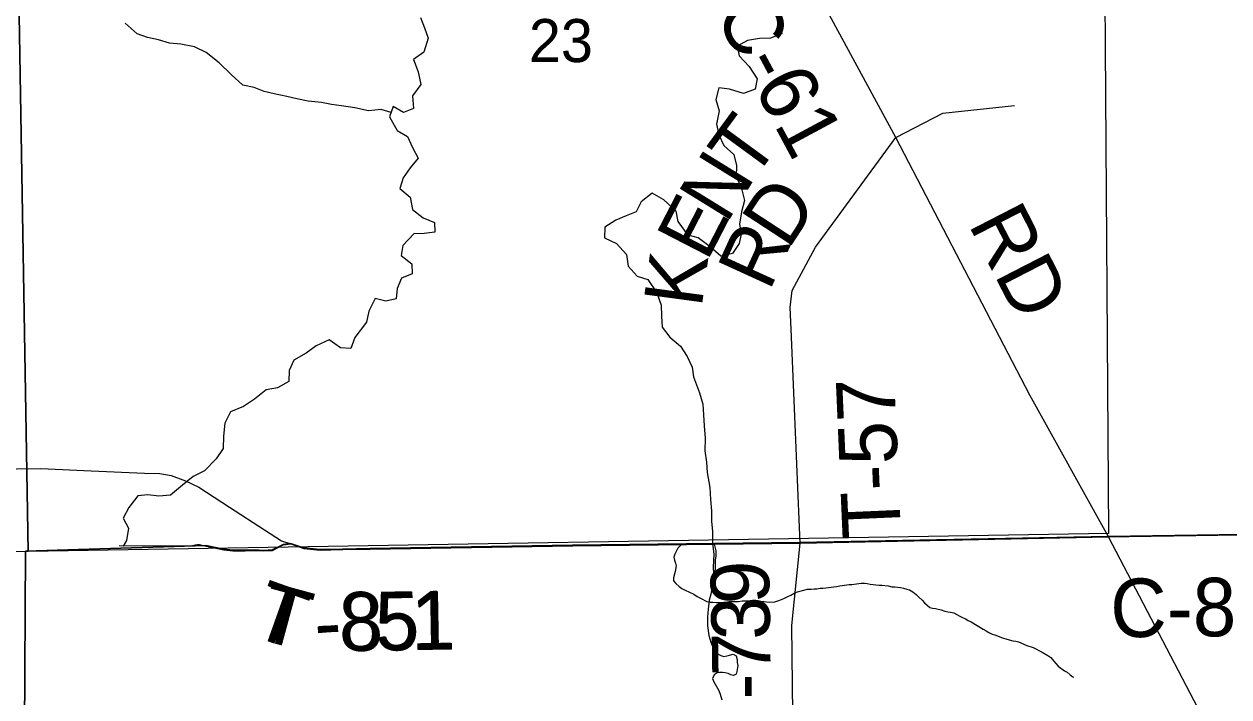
# Model space of a CAD drawing. Extents: x 0 to 34, y 0 to 22.
# Drawn here: x 3.443 to 4.614, y 19.097 to 19.751 of the extents above; entities that cross this region are included whole.
import ezdxf

# ---------------------------------------------------------------- set-up
doc = ezdxf.new("R2010")
doc.units = 0
for name, color, linetype in [('GM_X_County_Road', 7, 'Continuous'), ('GM_X_County_Road_Text', 7, 'Continuous'), ('GM_X_Minor_River', 7, 'Continuous'), ('GM_X_Rail_Line', 7, 'Continuous'), ('GM_X_Section', 7, 'Continuous'), ('GM_X_Section_Text', 7, 'Continuous'), ('GM_X_Township', 7, 'Continuous'), ('GM_X_Township_Road', 7, 'Continuous'), ('GM_X_Township_Road_Text', 7, 'Continuous'), ('SH_Cut_Line', 7, 'Continuous')]:
    doc.layers.add(name, color=color, linetype=linetype)

msp = doc.modelspace()

# ---------------------------------------------------------------- linework, layer by layer
at = {"layer": 'GM_X_County_Road'}
msp.add_line((4.497, 19.2526), (4.5168, 19.2529), dxfattribs=at)
for points in [[(4.497, 19.2526), (4.4208, 19.3901), (4.2904, 19.6406), (4.1777, 19.8488), (4.1636, 19.8791), (4.1541, 19.9074), (4.1442, 19.9366), (4.1303, 19.9782), (4.1198, 20.013), (4.1112, 20.041), (4.093, 20.0955), (4.0874, 20.1167), (4.0803, 20.1337), (4.0339, 20.1931), (4.0167, 20.23), (4.0013, 20.2492)], [(4.5168, 19.2529), (4.9933, 19.26), (5.2151, 19.2619), (5.5233, 19.2646)], [(4.634, 18.9904), (4.6257, 19.0064), (4.497, 19.2526)]]:
    msp.add_lwpolyline(points, dxfattribs=at)
at = {"layer": 'GM_X_Minor_River'}
for points in [[(3.8287, 19.757), (3.8326, 19.7472), (3.8361, 19.737), (3.832, 19.7236), (3.8219, 19.7163), (3.8265, 19.7042), (3.8289, 19.6921), (3.8207, 19.681), (3.8219, 19.6688), (3.8121, 19.665), (3.8022, 19.6706), (3.7985, 19.6607), (3.8058, 19.6474), (3.8161, 19.6414), (3.8208, 19.6309), (3.8262, 19.6206), (3.8187, 19.6111), (3.8119, 19.6015), (3.8086, 19.5909), (3.8186, 19.5826), (3.8209, 19.5705), (3.8312, 19.5626), (3.8423, 19.5581), (3.8424, 19.5486), (3.8321, 19.5474), (3.8223, 19.5469), (3.8114, 19.5358), (3.81, 19.5259), (3.8203, 19.5177), (3.8204, 19.5082), (3.8102, 19.5039), (3.8058, 19.494), (3.8051, 19.4837), (3.7949, 19.4817), (3.7846, 19.4843), (3.7783, 19.4717), (3.7762, 19.4611), (3.7649, 19.4462), (3.7609, 19.4355), (3.751, 19.4362), (3.74, 19.4441), (3.7272, 19.4383), (3.7174, 19.4309), (3.7057, 19.4244), (3.7009, 19.4141), (3.7006, 19.4035), (3.6897, 19.3973), (3.6787, 19.3953), (3.6674, 19.3865), (3.6565, 19.3792), (3.6441, 19.3741), (3.6385, 19.3631), (3.6371, 19.3505), (3.6368, 19.3384), (3.6301, 19.3284), (3.6189, 19.3166), (3.6079, 19.3111), (3.5974, 19.3027), (3.5858, 19.2931), (3.5744, 19.2922), (3.5638, 19.2933), (3.554, 19.2924), (3.5454, 19.281), (3.5398, 19.2707), (3.5448, 19.2609), (3.543, 19.2491), (3.5397, 19.2437)], [(3.8, 19.6647), (3.7905, 19.6678), (3.778, 19.6666), (3.7647, 19.6695), (3.7519, 19.6713), (3.742, 19.6727), (3.7325, 19.6745), (3.7196, 19.6759), (3.7086, 19.6781), (3.6988, 19.6803), (3.6866, 19.6829), (3.6768, 19.6851), (3.6669, 19.6892), (3.6559, 19.6914), (3.6448, 19.7019), (3.633, 19.7132), (3.6204, 19.723), (3.609, 19.7286), (3.5957, 19.7311), (3.5847, 19.7321), (3.5741, 19.7355), (3.5635, 19.7377), (3.5532, 19.7414), (3.5418, 19.7515)], [(4.1759, 19.7516), (4.1798, 19.7414), (4.1688, 19.7371), (4.1579, 19.7367), (4.1465, 19.7347), (4.1363, 19.7293), (4.1383, 19.7198), (4.1479, 19.7096), (4.1556, 19.6975), (4.1538, 19.6876), (4.1424, 19.6834), (4.1288, 19.6874), (4.1185, 19.6889), (4.1156, 19.6774), (4.1188, 19.6664), (4.1162, 19.6535), (4.1186, 19.6433), (4.1232, 19.6327), (4.1332, 19.624), (4.1355, 19.6134), (4.1353, 19.6024), (4.1403, 19.5922), (4.1434, 19.5793), (4.1405, 19.5683), (4.1387, 19.5565), (4.1403, 19.547), (4.1381, 19.5375), (4.1318, 19.5279), (4.1204, 19.5252), (4.1101, 19.5342), (4.0983, 19.5432), (4.0888, 19.5458), (4.0789, 19.559), (4.0769, 19.5689), (4.065, 19.5801), (4.0536, 19.5865), (4.0431, 19.5781), (4.0383, 19.5685), (4.0285, 19.5646), (4.0183, 19.5604), (4.0077, 19.5535), (4.0075, 19.5432), (4.0189, 19.5376), (4.0288, 19.527), (4.0304, 19.5157), (4.0392, 19.5059), (4.0495, 19.5025), (4.0583, 19.4897), (4.0626, 19.4776), (4.0627, 19.4669), (4.0635, 19.4563), (4.0708, 19.4465), (4.0811, 19.4379), (4.0877, 19.4277), (4.0927, 19.4174), (4.0939, 19.408), (4.0997, 19.3924), (4.1029, 19.3815)], [(4.1029, 19.3815), (4.1037, 19.3712), (4.1042, 19.3606), (4.1051, 19.3484), (4.1048, 19.3363), (4.1064, 19.3253), (4.1073, 19.315), (4.1097, 19.3006), (4.1105, 19.2888), (4.1114, 19.2778), (4.1115, 19.2676), (4.1123, 19.2581), (4.1124, 19.2467), (4.1137, 19.2353), (4.113, 19.2232), (4.1135, 19.2106), (4.1139, 19.2072)], [(4.082, 19.2447), (4.0786, 19.2416), (4.0757, 19.2359), (4.0749, 19.2328), (4.0754, 19.2298), (4.0765, 19.2272), (4.0769, 19.2245), (4.0762, 19.2188), (4.0744, 19.2127), (4.0744, 19.21), (4.0768, 19.2074), (4.0798, 19.2044), (4.0825, 19.2025), (4.0859, 19.2007), (4.0943, 19.197), (4.0974, 19.1947), (4.1008, 19.1929), (4.1069, 19.1899), (4.11, 19.1892), (4.1126, 19.1892), (4.116, 19.1889), (4.1225, 19.1889), (4.1255, 19.1893), (4.1282, 19.1898), (4.1376, 19.1899), (4.141, 19.1903), (4.1475, 19.1904), (4.1532, 19.1912), (4.1562, 19.1909), (4.1593, 19.1901), (4.1676, 19.1891), (4.1729, 19.1895), (4.1759, 19.1903), (4.1793, 19.1919), (4.1824, 19.1931), (4.1854, 19.1946), (4.1884, 19.1958), (4.1922, 19.1981), (4.1948, 19.1993), (4.2046, 19.2017), (4.2081, 19.2017), (4.2111, 19.2022), (4.2137, 19.2022), (4.2168, 19.2026), (4.2194, 19.2026), (4.2224, 19.203), (4.2327, 19.2043), (4.2361, 19.2051), (4.2452, 19.2064), (4.2478, 19.2064), (4.2569, 19.2076), (4.2599, 19.2077), (4.2626, 19.2073), (4.2656, 19.2066), (4.274, 19.2056), (4.277, 19.2056), (4.2831, 19.2049), (4.2865, 19.2042), (4.2896, 19.2042), (4.2949, 19.2035), (4.2979, 19.2028), (4.301, 19.2017), (4.3036, 19.201), (4.3071, 19.1991), (4.3101, 19.1965), (4.3128, 19.1939), (4.3159, 19.1912), (4.3182, 19.1886), (4.3236, 19.1841), (4.3262, 19.1834), (4.3289, 19.183), (4.3346, 19.1816), (4.338, 19.1805), (4.3411, 19.1797), (4.3437, 19.1794), (4.3468, 19.1787), (4.3525, 19.1757), (4.3552, 19.1742), (4.3582, 19.1731), (4.3609, 19.1712), (4.3635, 19.1701), (4.3754, 19.163), (4.3781, 19.1612), (4.3807, 19.1597), (4.3842, 19.1582), (4.3868, 19.1575), (4.3941, 19.1545), (4.3983, 19.1531), (4.404, 19.1516), (4.407, 19.1513), (4.4097, 19.1505), (4.4177, 19.1472), (4.4238, 19.145), (4.4325, 19.1405), (4.4383, 19.1372), (4.4409, 19.1353), (4.4436, 19.1323), (4.4482, 19.127), (4.4544, 19.1225), (4.457, 19.1211), (4.4597, 19.1184)], [(4.1139, 19.2456), (4.1155, 19.239), (4.1155, 19.2337), (4.1148, 19.2303), (4.1149, 19.2219), (4.1142, 19.2154), (4.1128, 19.209), (4.1124, 19.2063), (4.1106, 19.1968), (4.1092, 19.1911), (4.1081, 19.1823), (4.1075, 19.1747), (4.1076, 19.1663), (4.1088, 19.1568), (4.1096, 19.1534), (4.1108, 19.1504), (4.112, 19.147), (4.1135, 19.144), (4.1154, 19.1413), (4.1177, 19.1387), (4.1204, 19.1372), (4.1235, 19.1365), (4.1261, 19.1369), (4.1288, 19.1377), (4.1325, 19.1385), (4.1352, 19.137), (4.1364, 19.1336), (4.1364, 19.1306), (4.1368, 19.1275), (4.1361, 19.1218), (4.1354, 19.1191), (4.1328, 19.118), (4.1301, 19.1187), (4.1274, 19.1198), (4.1248, 19.1205), (4.1221, 19.1209), (4.1195, 19.1209), (4.1168, 19.1204), (4.1138, 19.1185), (4.1123, 19.1151), (4.1135, 19.1117), (4.1185, 19.1034), (4.1197, 19.0999), (4.1213, 19.0943)], [(4.4597, 19.1184), (4.4624, 19.1166), (4.4632, 19.1162)]]:
    msp.add_lwpolyline(points, dxfattribs=at)
at = {"layer": 'GM_X_Rail_Line'}
msp.add_lwpolyline([(3.4553, 18.2338), (3.4545, 18.2877), (3.4435, 18.9899), (3.4436, 19.0062), (3.4449, 19.2386), (3.6201, 19.2441), (3.6278, 19.2425), (3.6373, 19.2406), (3.6462, 19.2397), (3.6581, 19.2397), (3.6674, 19.24), (3.6763, 19.2395), (3.6845, 19.24), (3.6951, 19.2453), (3.7023, 19.2463), (3.715, 19.2418), (3.7309, 19.2404), (3.753, 19.2407), (3.7796, 19.2412), (3.9763, 19.2445), (4.1973, 19.2471), (4.4968, 19.2531), (4.9931, 19.2605)], dxfattribs=at)
at = {"layer": 'GM_X_Section'}
for points in [[(3.4305, 20.2427), (3.4475, 19.2384), (2.4219, 19.2256), (2.4052, 20.2337)], [(4.4904, 20.2497), (4.497, 19.2557), (3.4475, 19.2384), (3.4305, 20.2427)]]:
    msp.add_lwpolyline(points, close=True, dxfattribs=at)
at = {"layer": 'GM_X_Township'}
msp.add_lwpolyline([(3.4553, 18.2338), (3.4545, 18.2877), (3.4435, 18.9899), (3.4436, 19.0062), (3.4449, 19.2386), (3.6201, 19.2441), (3.6278, 19.2425), (3.6373, 19.2406), (3.6462, 19.2397), (3.6581, 19.2397), (3.6674, 19.24), (3.6763, 19.2395), (3.6845, 19.24), (3.6951, 19.2453), (3.7023, 19.2463), (3.715, 19.2418), (3.7309, 19.2404), (3.753, 19.2407), (3.7796, 19.2412), (3.9763, 19.2445), (4.1973, 19.2471), (4.4968, 19.2531), (4.9931, 19.2605)], dxfattribs=at)
at = {"layer": 'GM_X_Township_Road'}
for p, q in [((4.1975, 19.2466), (4.497, 19.2526)), ((4.497, 19.2526), (4.5168, 19.2529))]:
    msp.add_line(p, q, dxfattribs=at)
for points in [[(4.2904, 19.6406), (4.3361, 19.6643), (4.4056, 19.6718)], [(4.1975, 19.2466), (4.1887, 19.4545), (4.1879, 19.4754), (4.1898, 19.4918), (4.2125, 19.5341), (4.2904, 19.6406)], [(2.9238, 19.2285), (3.0142, 19.2286), (3.1101, 19.2967), (3.1285, 19.308), (3.1414, 19.314), (3.1508, 19.3153), (3.3403, 19.3173), (3.4121, 19.3185), (3.4598, 19.3189), (3.5087, 19.3169), (3.5604, 19.3146), (3.5753, 19.3142), (3.5864, 19.3122), (3.6002, 19.3071), (3.6132, 19.3008), (3.6432, 19.2814), (3.6771, 19.2594), (3.6937, 19.2487), (3.7025, 19.2457)], [(4.5168, 19.2529), (4.9933, 19.26), (5.2151, 19.2619), (5.5233, 19.2646)], [(3.5357, 19.2442), (3.6059, 19.244), (3.6096, 19.2449), (3.6119, 19.2452), (3.614, 19.2451), (3.6164, 19.2445), (3.6203, 19.2435)], [(3.6203, 19.2435), (3.628, 19.2419), (3.6375, 19.24), (3.6464, 19.2391), (3.6583, 19.2391), (3.6676, 19.2394), (3.6765, 19.2389), (3.6847, 19.2394), (3.6953, 19.2448), (3.7025, 19.2457)], [(3.7025, 19.2457), (3.7152, 19.2412), (3.7311, 19.2398), (3.7522, 19.2402)], [(3.7522, 19.2402), (3.7532, 19.2402), (3.7798, 19.2407), (3.9765, 19.244), (4.1975, 19.2466)], [(4.1908, 19.0515), (4.1894, 19.1665), (4.1975, 19.2466)]]:
    msp.add_lwpolyline(points, dxfattribs=at)
at = {"layer": 'SH_Cut_Line'}
for points in [[(3.4553, 18.2338), (3.4545, 18.2877), (3.4435, 18.9899), (3.4436, 19.0062), (3.4449, 19.2386), (3.6201, 19.2441), (3.6278, 19.2425), (3.6373, 19.2406), (3.6462, 19.2397), (3.6581, 19.2397), (3.6674, 19.24), (3.6763, 19.2395), (3.6845, 19.24), (3.6951, 19.2453), (3.7023, 19.2463), (3.715, 19.2418), (3.7309, 19.2404), (3.753, 19.2407), (3.7796, 19.2412), (3.9763, 19.2445), (4.1973, 19.2471), (4.4968, 19.2531), (4.9931, 19.2605)], [(4.9931, 19.2605), (4.4968, 19.2531), (4.1973, 19.2471), (3.9763, 19.2445), (3.7796, 19.2412), (3.753, 19.2407), (3.7309, 19.2404), (3.715, 19.2418), (3.7023, 19.2463), (3.6951, 19.2453), (3.6845, 19.24), (3.6763, 19.2395), (3.6674, 19.24), (3.6581, 19.2397), (3.6462, 19.2397), (3.6373, 19.2406), (3.6278, 19.2425), (3.6201, 19.2441), (3.4449, 19.2386), (3.4436, 19.0062), (3.4435, 18.9899), (3.4545, 18.2877), (3.4553, 18.2338)]]:
    msp.add_lwpolyline(points, dxfattribs=at)

# ---------------------------------------------------------------- texts
at = {"layer": 'GM_X_County_Road_Text'}
for s, rotation, p in [('C-61', 298.2551, (4.1136, 19.7612)), ('RD', 297.2275, (4.3604, 19.5565)), ('C-851', 0.5506, (4.499, 19.155))]:
    msp.add_text(s, height=0.05682, rotation=rotation, dxfattribs=at).set_placement(p)
at = {"layer": 'GM_X_Section_Text'}
msp.add_text('23', height=0.04186, rotation=0, dxfattribs=at).set_placement((3.9339, 19.7138))
at = {"layer": 'GM_X_Township_Road_Text'}
for s, height, rotation, p in [('T', 0.0568, 53.8214, (4.1513, 19.5973)), ('N', 0.0568, 58.3209, (4.1257, 19.5557)), ('D', 0.0568, 56.8494, (4.1858, 19.5307)), ('E', 0.0568, 62.7335, (4.1068, 19.519)), ('R', 0.0568, 65.4383, (4.1675, 19.4902)), ('K', 0.0568, 82.3382, (4.1017, 19.4743)), ('T-57', 0.05682, 92.4742, (4.2956, 19.2521)), ('9', 0.0568, 91.1662, (4.1678, 19.1878)), ('T', 0.0568, 340.4131, (3.6615, 19.1578)), ('T', 0.0568, 344.784, (3.6681, 19.1541)), ('8', 0.0568, 0.7078, (3.7496, 19.142)), ('8', 0.0568, 0.5933, (3.7504, 19.1416)), ('5', 0.0568, 0.9294, (3.7848, 19.1424)), ('5', 0.0568, 0.9216, (3.7857, 19.142)), ('1', 0.0568, 0.9717, (3.8198, 19.143)), ('1', 0.0568, 1.0047, (3.8208, 19.1425)), ('3', 0.0568, 90.9861, (4.1684, 19.1529)), ('-', 0.0568, 4.6712, (3.7273, 19.1401)), ('-', 0.0568, 1.9097, (3.7274, 19.1408)), ('7', 0.0568, 90.8133, (4.1689, 19.118)), ('-', 0.0568, 90.7154, (4.1692, 19.0948))]:
    msp.add_text(s, height=height, rotation=rotation, dxfattribs=at).set_placement(p)

doc.saveas('drawing.dxf')
